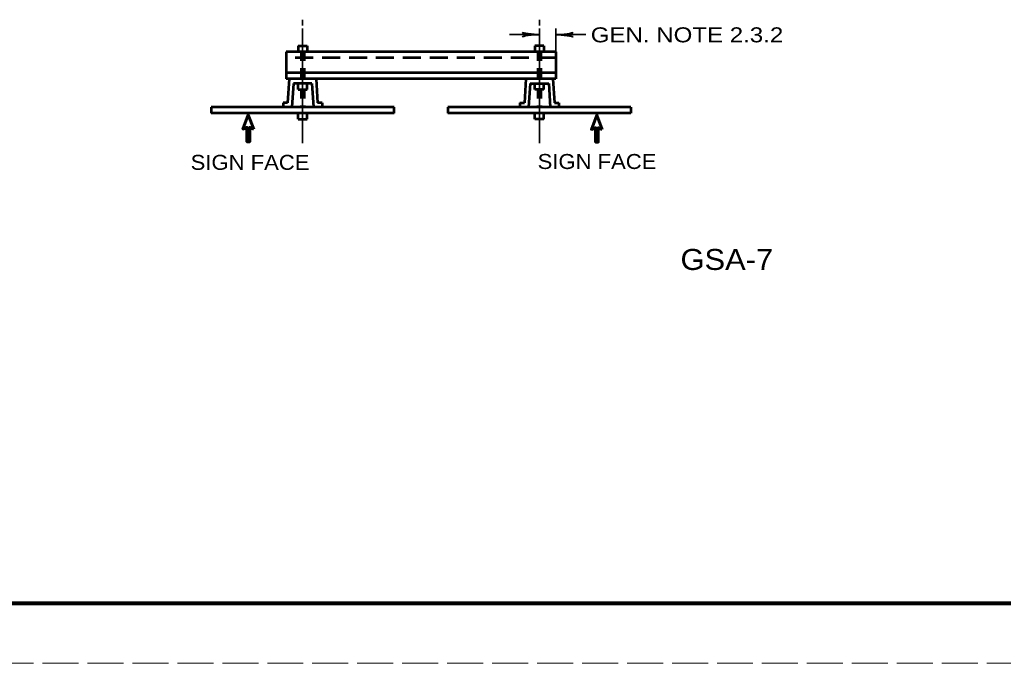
# Model space of a CAD drawing. Extents: x -45 to 635, y -382 to 59.
# Drawn here: x 287.9 to 451.9, y -381.5 to -274.1 of the extents above; entities that cross this region are included whole.
import ezdxf
from ezdxf.enums import TextEntityAlignment as Align

# ---------------------------------------------------------------- set-up
doc = ezdxf.new("R2010")
doc.units = 0
for name, pattern in [('LONG_DASHED', [7.5, 6, -1.5]), ('MEDIUM_DASHED', [4.5, 3, -1.5]), ('SHORT_DASHED', [2.7, 1.5, -1.2])]:
    doc.linetypes.add(name, pattern=pattern)
doc.layers.add('1', color=7, linetype='Continuous', lineweight=53)
doc.layers.add('61', color=7, linetype='Continuous', lineweight=35)

msp = doc.modelspace()

# ---------------------------------------------------------------- linework, layer by layer
at = {"layer": '1', "lineweight": 35}
for p, q in [((335.05, -274.11), (335.05, -275.11)), ((335.05, -275.61), (335.05, -278.485)), ((374.55, -274.11), (374.55, -275.11)), ((374.55, -275.61), (374.55, -278.485)), ((377.29, -279.485), (377.29, -275.61)), ((369.55, -276.61), (374.55, -276.61)), ((377.29, -276.61), (382.29, -276.61)), ((335.05, -278.485), (335.05, -294.735)), ((374.55, -278.485), (374.55, -294.735))]:
    msp.add_line(p, q, dxfattribs=at)
at = {"layer": '1'}
for p, q in [((334.3, -278.485), (335.8, -278.485)), ((334.3, -278.485), (334.3, -279.485)), ((335.8, -278.485), (335.8, -279.485)), ((375.3, -278.485), (373.8, -278.485)), ((373.8, -278.485), (373.8, -279.485)), ((375.3, -278.485), (375.3, -279.485)), ((377.29, -279.485), (332.31, -279.485)), ((332.31, -279.485), (332.31, -283.985)), ((377.29, -279.485), (377.29, -283.985)), ((377.29, -282.985), (332.31, -282.985)), ((377.29, -283.985), (332.31, -283.985)), ((332.8, -283.985), (332.55, -287.985)), ((333.504, -284.735), (333.254, -288.735)), ((336.595, -284.735), (333.504, -284.735)), ((334.3, -285.735), (334.3, -284.735)), ((335.8, -285.735), (335.8, -284.735)), ((336.595, -284.735), (336.845, -288.735)), ((337.3, -283.985), (337.55, -287.985)), ((372.3, -283.985), (372.05, -287.985)), ((373.004, -284.735), (372.754, -288.735)), ((373.004, -284.735), (376.095, -284.735)), ((373.8, -285.735), (373.8, -284.735)), ((375.3, -285.735), (375.3, -284.735)), ((376.095, -284.735), (376.345, -288.735)), ((376.8, -283.985), (377.05, -287.985)), ((334.3, -285.735), (335.8, -285.735)), ((375.3, -285.735), (373.8, -285.735)), ((350.3, -288.735), (319.8, -288.735)), ((319.8, -288.735), (319.8, -289.735)), ((332.55, -287.985), (331.8, -287.985)), ((331.8, -287.985), (331.8, -288.735)), ((338.3, -287.985), (337.55, -287.985)), ((338.3, -287.985), (338.3, -288.735)), ((350.3, -289.735), (350.3, -288.735)), ((389.8, -288.735), (359.3, -288.735)), ((359.3, -288.735), (359.3, -289.735)), ((371.3, -287.985), (372.05, -287.985)), ((371.3, -287.985), (371.3, -288.735)), ((377.05, -287.985), (377.8, -287.985)), ((377.8, -287.985), (377.8, -288.735)), ((389.8, -288.735), (389.8, -289.735)), ((350.3, -289.735), (319.8, -289.735)), ((334.3, -290.735), (334.3, -289.735)), ((335.8, -290.735), (335.8, -289.735)), ((389.8, -289.735), (359.3, -289.735)), ((373.8, -290.735), (373.8, -289.735)), ((375.3, -290.735), (375.3, -289.735)), ((334.3, -290.735), (335.8, -290.735)), ((375.3, -290.735), (373.8, -290.735))]:
    msp.add_line(p, q, dxfattribs=at)
at = {"layer": '1', "linetype": 'MEDIUM_DASHED'}
msp.add_line((377.29, -280.485), (332.31, -280.485), dxfattribs=at)
at = {"layer": '1', "linetype": 'SHORT_DASHED'}
for p, q in [((334.8, -279.485), (334.8, -283.985)), ((335.3, -279.485), (335.3, -283.985)), ((374.3, -279.485), (374.3, -283.985)), ((374.8, -279.485), (374.8, -283.985)), ((334.8, -285.735), (334.8, -288.735)), ((335.3, -285.735), (335.3, -288.735)), ((374.3, -285.735), (374.3, -288.735)), ((374.8, -285.735), (374.8, -288.735))]:
    msp.add_line(p, q, dxfattribs=at)
at = {"layer": '1', "lineweight": 60}
for points in [[(326.896, -292.356), (325.996, -289.971), (325.096, -292.356), (325.771, -292.086), (325.771, -294.471), (326.221, -294.471), (326.221, -292.086)], [(385.029, -292.426), (384.129, -290.041), (383.229, -292.426), (383.904, -292.156), (383.904, -294.541), (384.354, -294.541), (384.354, -292.156)]]:
    msp.add_lwpolyline(points, close=True, dxfattribs=at)
at = {"layer": '1', "lineweight": 40}
for centre, major_axis, ratio, start_param, end_param in [((373.458, -276.886), (1.786, 0.156), 0.122415, 0.8963533, 3.1415927), ((373.429, -276.399), (1.756, -0.176), 0.07063, 3.1407148, 5.41811), ((378.41, -276.822), (-1.756, 0.176), 0.07063, 3.1407148, 5.41811), ((378.41, -276.822), (-1.756, 0.176), 0.07063, 3.1407148, 5.41811), ((378.381, -276.334), (-1.786, -0.156), 0.122415, 0.8963533, 3.1415927), ((378.381, -276.334), (-1.786, -0.156), 0.122415, 0.8963533, 3.1415927)]:
    msp.add_ellipse(centre, major_axis=major_axis, ratio=ratio, start_param=start_param, end_param=end_param, dxfattribs=at)
at = {"layer": '61', "lineweight": 158}
msp.add_line((624.229, -371.5), (-14.831, -371.48), dxfattribs=at)
at = {"layer": '61', "linetype": 'LONG_DASHED', "lineweight": 13}
msp.add_line((635.169, -381.48), (-44.891, -381.5), dxfattribs=at)

# ---------------------------------------------------------------- texts
at = {"layer": '1'}
for s, height, width, p in [('GEN. NOTE 2.3.2', 2.5, 1.2, (399.166, -277.891)), ('SIGN FACE', 2.5, 1.1, (326.281, -299.166)), ('SIGN FACE', 2.5, 1.1, (384.156, -299.024)), ('GSA-7', 3.5, 1.1, (405.806, -315.868))]:
    msp.add_text(s, height=height, dxfattribs=dict(at, width=width)).set_placement(p, align=Align.CENTER)

doc.saveas('drawing.dxf')
